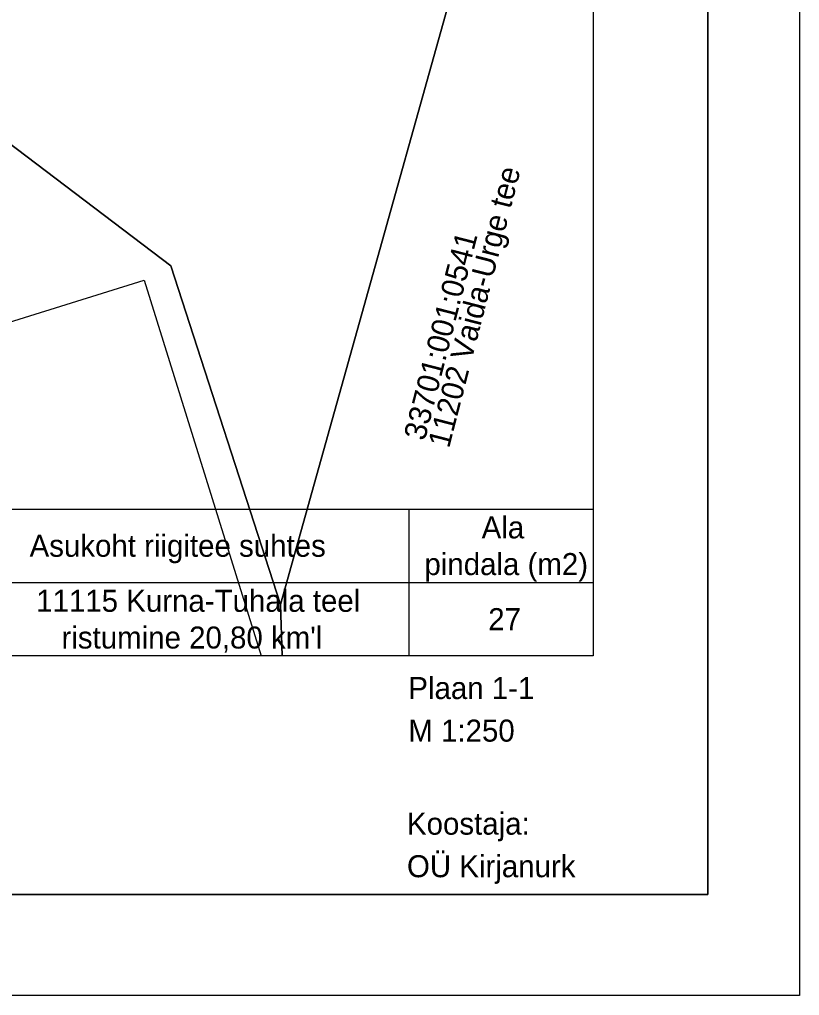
# Model space of a CAD drawing. Extents: x 555018.3 to 555070.8, y 6565612.3 to 6565686.5.
# Drawn here: x 555049.49 to 555070.75, y 6565612.26 to 6565638.85 of the extents above; entities that cross this region are included whole.
import ezdxf

# ---------------------------------------------------------------- set-up
doc = ezdxf.new("R2010")
doc.units = 0
for name, color, linetype in [('Hoone Vare', 7, 'Continuous'), ('PIIR', 7, 'Continuous'), ('VORMISTUS', 7, 'Continuous')]:
    doc.layers.add(name, color=color, linetype=linetype)

msp = doc.modelspace()

# ---------------------------------------------------------------- linework, layer by layer
at = {"layer": 'Hoone Vare'}
msp.add_lwpolyline([(555047.832, 6565621.515), (555045.371, 6565629.41), (555052.886, 6565631.752), (555056.077, 6565621.515)], dxfattribs=at)
at = {"layer": 'PIIR'}
for points in [[(555023.875, 6565665.204), (555047.17, 6565654.02), (555063.43, 6565647.29), (555056.61, 6565622.91), (555053.62, 6565632.14), (555043.11, 6565640.11), (555030.24, 6565648.23), (555023.875, 6565651.228)], [(555023.875, 6565651.228), (555030.24, 6565648.23), (555043.11, 6565640.11), (555053.62, 6565632.14), (555056.61, 6565622.91), (555056.648, 6565621.515)], [(555056.648, 6565621.515), (555056.61, 6565622.91), (555063.43, 6565647.29), (555065.125, 6565646.847)]]:
    msp.add_lwpolyline(points, dxfattribs=at)
at = {"layer": 'VORMISTUS'}
for p, q in [((555060.1, 6565625.515), (555060.1, 6565621.515)), ((555023.875, 6565623.515), (555065.125, 6565623.515))]:
    msp.add_line(p, q, dxfattribs=at)
for points in [[(555018.25, 6565686.515), (555070.75, 6565686.515), (555070.75, 6565612.265), (555018.25, 6565612.265)], [(555020.75, 6565615.015), (555068.25, 6565615.015), (555068.25, 6565683.765), (555020.75, 6565683.765)], [(555020.75, 6565683.765), (555068.25, 6565683.765), (555068.25, 6565615.015), (555020.75, 6565615.015)], [(555065.125, 6565621.515), (555023.875, 6565621.515), (555023.875, 6565674.015), (555065.125, 6565674.015)], [(555023.875, 6565625.515), (555065.125, 6565625.515), (555065.125, 6565621.515), (555023.875, 6565621.515)]]:
    msp.add_lwpolyline(points, close=True, dxfattribs=at)

# ---------------------------------------------------------------- texts
at = {"layer": 'PIIR'}
for s, p in [('11202 Vaida-Urge tee', (555061.199, 6565627.15)), ('33701:001:0541', (555060.537, 6565627.351))]:
    msp.add_text(s, height=0.6, rotation=75.5795, dxfattribs=at).set_placement(p)
at = {"layer": 'VORMISTUS'}
for s, p in [('Ala', (555062.088, 6565624.715)), ('Asukoht riigitee suhtes ', (555049.768, 6565624.215)), ('pindala (m2)', (555060.529, 6565623.715)), ('11115 Kurna-Tuhala teel', (555049.948, 6565622.715)), ('27', (555062.268, 6565622.215)), ("ristumine 20,80 km'l", (555050.638, 6565621.715))]:
    msp.add_text(s, height=0.6, dxfattribs=at).set_placement(p)
for s, p in [('Plaan 1-1', (555060.09, 6565620.339)), ('M 1:250', (555060.09, 6565619.179)), ('Koostaja:', (555060.053, 6565616.645)), ('OÜ Kirjanurk', (555060.053, 6565615.486))]:
    msp.add_text(s, height=0.6, rotation=360, dxfattribs=at).set_placement(p)

doc.saveas('drawing.dxf')
